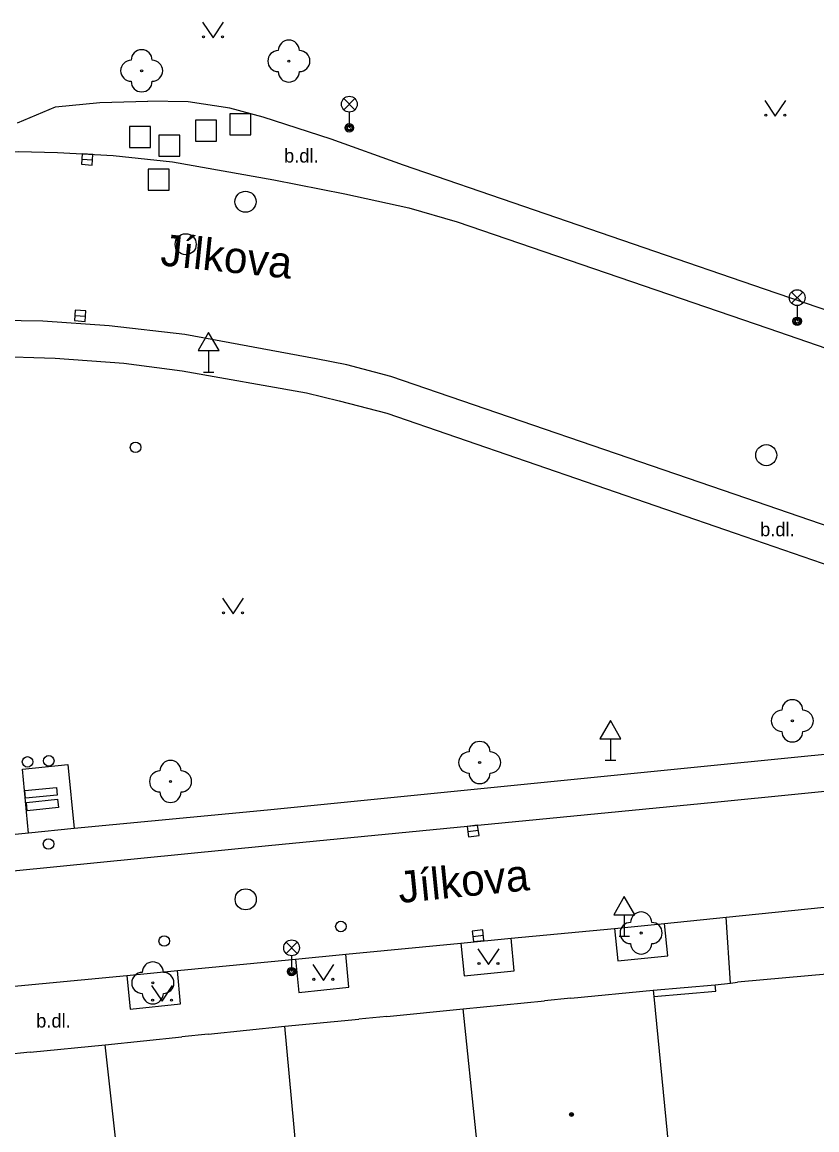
# Model space of a CAD drawing. Extents: x -596229 to -595156, y -1161237 to -1159376.
# Drawn here: x -596183.9 to -596146.2, y -1160892.5 to -1160839.9 of the extents above; entities that cross this region are included whole.
import ezdxf

# ---------------------------------------------------------------- set-up
doc = ezdxf.new("R2010")
doc.units = 0
for name, color, linetype in [('Level 22', 7, 'Continuous'), ('Level 26', 7, 'Continuous'), ('Level 27', 7, 'Continuous'), ('Level 28', 7, 'Continuous'), ('Level 31', 7, 'Continuous'), ('Level 33', 7, 'Continuous'), ('Level 34', 7, 'Continuous'), ('Level 36', 7, 'Continuous'), ('Level 39', 7, 'Continuous'), ('Nazvy ulic', 7, 'Continuous'), ('plynovod - povrch.  znaky - PRIS skut. velikost', 7, 'Continuous'), ('TM - budovy zdene_ betonove - VP', 7, 'Continuous'), ('TM - chodniky - VP', 7, 'Continuous'), ('TM - komunikace - VP', 7, 'Continuous'), ('TM - plot drateny_ kovovy - VP', 7, 'Continuous'), ('TM - plot zdeny_ ohradni zed - VP', 7, 'Continuous'), ('TM - podezdivka plotu - VP', 7, 'Continuous'), ('TM - popis povrchu', 7, 'Continuous'), ('TM - rozhrani mezi zpev. plochami mezi sebou - VP', 7, 'Continuous'), ('TM - rozhrani ploch obecne - VP', 7, 'Continuous'), ('TM - vjezd na pozemek', 7, 'Continuous'), ('TM - vstup do budovy - zdene_ betonove', 7, 'Continuous')]:
    doc.layers.add(name, color=color, linetype=linetype)

msp = doc.modelspace()

# ---------------------------------------------------------------- linework, layer by layer
at = {"layer": 'Level 22'}
for centre in [(-596171.24, -1160841.74), (-596178.23, -1160842.2), (-596147.33, -1160873.08), (-596162.18, -1160875.06), (-596176.86, -1160875.96), (-596154.51, -1160883.16), (-596177.7, -1160885.53)]:
    msp.add_circle(centre, 0.05, dxfattribs=at)
for centre, start, end in [((-596171.24, -1160841.24), 0, 180), ((-596178.23, -1160841.7), 0, 180), ((-596171.74, -1160841.74), 90, 270), ((-596170.74, -1160841.74), 270, 90), ((-596178.73, -1160842.2), 90, 270), ((-596177.73, -1160842.2), 270, 90), ((-596171.24, -1160842.24), 180, 0), ((-596178.23, -1160842.7), 180, 0), ((-596147.33, -1160872.58), 0, 180), ((-596147.83, -1160873.08), 90, 270), ((-596146.83, -1160873.08), 270, 90), ((-596147.33, -1160873.58), 180, 0), ((-596162.18, -1160874.56), 0, 180), ((-596176.86, -1160875.46), 0, 180), ((-596162.68, -1160875.06), 90, 270), ((-596161.68, -1160875.06), 270, 90), ((-596177.36, -1160875.96), 90, 270), ((-596176.36, -1160875.96), 270, 90), ((-596162.18, -1160875.56), 180, 0), ((-596176.86, -1160876.46), 180, 0), ((-596154.51, -1160882.66), 0, 180), ((-596155.01, -1160883.16), 90, 270), ((-596154.01, -1160883.16), 270, 90), ((-596154.51, -1160883.66), 180, 0), ((-596177.7, -1160885.03), 0, 180), ((-596178.2, -1160885.53), 90, 270), ((-596177.2, -1160885.53), 270, 90), ((-596177.7, -1160886.03), 180, 0)]:
    msp.add_arc(centre, 0.5, start, end, dxfattribs=at)
at = {"layer": 'Level 26'}
for points in [[(-596174.05, -1160845.24), (-596173.05, -1160845.24), (-596173.05, -1160844.24), (-596174.05, -1160844.24)], [(-596178.81, -1160845.84), (-596177.81, -1160845.84), (-596177.81, -1160844.84), (-596178.81, -1160844.84)], [(-596175.67, -1160845.54), (-596174.67, -1160845.54), (-596174.67, -1160844.54), (-596175.67, -1160844.54)], [(-596177.42, -1160846.26), (-596176.42, -1160846.26), (-596176.42, -1160845.26), (-596177.42, -1160845.26)], [(-596177.92, -1160847.87), (-596176.92, -1160847.87), (-596176.92, -1160846.87), (-596177.92, -1160846.87)]]:
    msp.add_lwpolyline(points, close=True, dxfattribs=at)
at = {"layer": 'Level 27'}
for p, q in [((-596181.069, -1160846.393), (-596180.571, -1160846.426)), ((-596181.399, -1160853.82), (-596180.901, -1160853.86)), ((-596162.738, -1160878.342), (-596162.242, -1160878.278)), ((-596162.498, -1160883.318), (-596162.002, -1160883.262))]:
    msp.add_line(p, q, dxfattribs=at)
for points in [[(-596181.086, -1160846.643), (-596180.587, -1160846.676), (-596180.554, -1160846.177), (-596181.053, -1160846.144)], [(-596181.419, -1160854.07), (-596180.92, -1160854.109), (-596180.881, -1160853.61), (-596181.38, -1160853.571)], [(-596162.706, -1160878.59), (-596162.21, -1160878.526), (-596162.274, -1160878.03), (-596162.77, -1160878.094)], [(-596162.47, -1160883.567), (-596161.973, -1160883.51), (-596162.03, -1160883.013), (-596162.527, -1160883.07)]]:
    msp.add_lwpolyline(points, close=True, dxfattribs=at)
for centre in [(-596173.3, -1160848.42), (-596176.14, -1160850.44), (-596148.57, -1160860.46), (-596173.29, -1160881.56)]:
    msp.add_circle(centre, 0.5, dxfattribs=at)
at = {"layer": 'Level 28'}
for centre in [(-596168.77, -1160882.85), (-596177.16, -1160883.54)]:
    msp.add_circle(centre, 0.25, dxfattribs=at)
at = {"layer": 'Level 31'}
for centre in [(-596178.52, -1160860.09), (-596183.65, -1160875.03), (-596182.64, -1160874.98), (-596182.65, -1160878.93)]:
    msp.add_circle(centre, 0.25, dxfattribs=at)
at = {"layer": 'Level 33'}
for p, q in [((-596168.635, -1160844.05), (-596168.105, -1160843.52)), ((-596168.635, -1160843.52), (-596168.105, -1160844.05)), ((-596168.37, -1160844.16), (-596168.37, -1160844.91)), ((-596147.365, -1160853.24), (-596146.835, -1160852.71)), ((-596147.365, -1160852.71), (-596146.835, -1160853.24)), ((-596147.1, -1160853.35), (-596147.1, -1160854.1)), ((-596171.375, -1160884.13), (-596170.845, -1160883.6)), ((-596171.375, -1160883.6), (-596170.845, -1160884.13)), ((-596171.11, -1160884.24), (-596171.11, -1160884.99))]:
    msp.add_line(p, q, dxfattribs=at)
for centre, radius in [((-596168.37, -1160843.785), 0.375), ((-596168.37, -1160844.91), 0.2), ((-596168.37, -1160844.91), 0.145), ((-596168.37, -1160844.91), 0.0876), ((-596147.1, -1160852.975), 0.375), ((-596147.1, -1160854.1), 0.2), ((-596147.1, -1160854.1), 0.145), ((-596147.1, -1160854.1), 0.0876), ((-596171.11, -1160883.865), 0.375), ((-596171.11, -1160884.99), 0.2), ((-596171.11, -1160884.99), 0.145), ((-596171.11, -1160884.99), 0.0876)]:
    msp.add_circle(centre, radius, dxfattribs=at)
at = {"layer": 'Level 34'}
for p, q in [((-596175.05, -1160855.492), (-596175.05, -1160856.51)), ((-596175.3, -1160856.51), (-596174.8, -1160856.51)), ((-596155.97, -1160873.932), (-596155.97, -1160874.95)), ((-596156.22, -1160874.95), (-596155.72, -1160874.95)), ((-596155.31, -1160882.292), (-596155.31, -1160883.31)), ((-596155.56, -1160883.31), (-596155.06, -1160883.31))]:
    msp.add_line(p, q, dxfattribs=at)
for points in [[(-596175.55, -1160855.492), (-596174.55, -1160855.492), (-596175.05, -1160854.626)], [(-596156.47, -1160873.932), (-596155.47, -1160873.932), (-596155.97, -1160873.066)], [(-596155.81, -1160882.292), (-596154.81, -1160882.292), (-596155.31, -1160881.426)]]:
    msp.add_lwpolyline(points, close=True, dxfattribs=at)
at = {"layer": 'Level 36'}
for points in [[(-596175.34, -1160839.89), (-596174.84, -1160840.64), (-596174.34, -1160839.89)], [(-596148.64, -1160843.61), (-596148.14, -1160844.36), (-596147.64, -1160843.61)], [(-596174.39, -1160867.25), (-596173.89, -1160868), (-596173.39, -1160867.25)], [(-596162.26, -1160883.91), (-596161.76, -1160884.66), (-596161.26, -1160883.91)], [(-596170.1, -1160884.66), (-596169.6, -1160885.41), (-596169.1, -1160884.66)], [(-596177.76, -1160885.65), (-596177.26, -1160886.4), (-596176.76, -1160885.65)]]:
    msp.add_lwpolyline(points, dxfattribs=at)
for centre in [(-596175.29, -1160840.59), (-596174.391, -1160840.59), (-596148.59, -1160844.31), (-596147.691, -1160844.31), (-596174.34, -1160867.95), (-596173.441, -1160867.95), (-596162.21, -1160884.61), (-596161.311, -1160884.61), (-596170.05, -1160885.36), (-596169.151, -1160885.36), (-596177.71, -1160886.35), (-596176.811, -1160886.35)]:
    msp.add_circle(centre, 0.05, dxfattribs=at)
at = {"layer": 'Level 39'}
for radius in [0.09, 0.0398]:
    msp.add_circle((-596157.82, -1160891.78), radius, dxfattribs=at)
at = {"layer": 'plynovod - povrch.  znaky - PRIS skut. velikost'}
for points in [[(-596183.78, -1160876.39), (-596182.28, -1160876.24), (-596182.24, -1160876.61), (-596183.74, -1160876.76), (-596183.78, -1160876.39)], [(-596183.7, -1160876.96), (-596182.22, -1160876.8), (-596182.18, -1160877.2), (-596183.66, -1160877.36), (-596183.7, -1160876.96)]]:
    msp.add_lwpolyline(points, dxfattribs=at)
at = {"layer": 'TM - budovy zdene_ betonove - VP'}
for points in [[(-596157.85, -1160886.26), (-596153.94, -1160885.87)], [(-596153.94, -1160885.87), (-596153.91, -1160886.17)], [(-596162.96, -1160886.76), (-596159.1, -1160886.38)], [(-596153.91, -1160886.17), (-596152.77, -1160897.86)], [(-596166.59, -1160887.12), (-596162.96, -1160886.76)], [(-596161.73, -1160898.67), (-596162.96, -1160886.76)], [(-596175.07, -1160887.97), (-596171.43, -1160887.59)], [(-596171.43, -1160887.59), (-596167.92, -1160887.25)], [(-596170.34, -1160899.44), (-596171.43, -1160887.59)], [(-596179.97, -1160888.47), (-596176.32, -1160888.09)], [(-596183.53, -1160888.82), (-596179.97, -1160888.47)], [(-596178.65, -1160900.3), (-596179.97, -1160888.47)]]:
    msp.add_lwpolyline(points, dxfattribs=at)
at = {"layer": 'TM - chodniky - VP'}
for points in [[(-596184.13, -1160844.68), (-596182.32, -1160843.92), (-596180.22, -1160843.7), (-596177.93, -1160843.65)], [(-596165.8, -1160846.69), (-596169.23, -1160845.45), (-596172.46, -1160844.41), (-596174.04, -1160843.97), (-596176.02, -1160843.68), (-596177.93, -1160843.65)], [(-596128.17, -1160859.58), (-596148.65, -1160852.57), (-596165.8, -1160846.69)], [(-596185.38, -1160855.75), (-596182.33, -1160855.85), (-596179.07, -1160856.09), (-596176.3, -1160856.45), (-596170.4, -1160857.5), (-596168.85, -1160857.88), (-596166.59, -1160858.47), (-596150.05, -1160864.16), (-596134.43, -1160869.55)], [(-596134.82, -1160873.59), (-596151.2, -1160875.22), (-596172.26, -1160877.32), (-596181.44, -1160878.2)], [(-596183.6, -1160878.41), (-596197.53, -1160879.81)], [(-596181.44, -1160878.2), (-596183.6, -1160878.41)], [(-596155.77, -1160882.94), (-596155.62, -1160884.48), (-596153.25, -1160884.24), (-596153.4, -1160882.71)], [(-596163.07, -1160883.64), (-596162.92, -1160885.2), (-596160.54, -1160884.96), (-596160.69, -1160883.41)], [(-596170.92, -1160884.4), (-596170.77, -1160885.98), (-596168.39, -1160885.73), (-596168.54, -1160884.17)], [(-596178.93, -1160885.17), (-596178.78, -1160886.77), (-596176.38, -1160886.53), (-596176.53, -1160884.94)]]:
    msp.add_lwpolyline(points, dxfattribs=at)
at = {"layer": 'TM - komunikace - VP'}
for points in [[(-596186.89, -1160846.14), (-596184.08, -1160846.04), (-596182.22, -1160846.08), (-596179.59, -1160846.23), (-596176.77, -1160846.52), (-596171.95, -1160847.38), (-596168.58, -1160848.04), (-596165.55, -1160848.71), (-596163.24, -1160849.38), (-596148.49, -1160854.43)], [(-596133.33, -1160868.07), (-596150.05, -1160862.33), (-596166.39, -1160856.73), (-596168.48, -1160856.17), (-596169.95, -1160855.88), (-596176.18, -1160854.72), (-596179.77, -1160854.31), (-596182.93, -1160854.09), (-596186.03, -1160854.05)], [(-596148.49, -1160854.43), (-596128.71, -1160861.25)], [(-596198.39, -1160881.6), (-596172.2, -1160879.01), (-596151.02, -1160876.94), (-596134.66, -1160875.31)], [(-596150.48, -1160882.41), (-596140.54, -1160881.39)], [(-596155.77, -1160882.94), (-596153.4, -1160882.71)], [(-596153.4, -1160882.71), (-596150.48, -1160882.41)], [(-596160.69, -1160883.41), (-596155.77, -1160882.94)], [(-596168.54, -1160884.17), (-596163.07, -1160883.64)], [(-596163.07, -1160883.64), (-596160.69, -1160883.41)], [(-596176.53, -1160884.94), (-596170.92, -1160884.4)], [(-596170.92, -1160884.4), (-596168.54, -1160884.17)], [(-596178.93, -1160885.17), (-596176.53, -1160884.94)], [(-596185.13, -1160885.77), (-596178.93, -1160885.17)]]:
    msp.add_lwpolyline(points, dxfattribs=at)
at = {"layer": 'TM - plot drateny_ kovovy - VP'}
for points in [[(-596150.26, -1160885.54), (-596149.94, -1160885.5)], [(-596150.99, -1160885.62), (-596150.26, -1160885.54)]]:
    msp.add_lwpolyline(points, dxfattribs=at)
at = {"layer": 'TM - plot zdeny_ ohradni zed - VP'}
msp.add_lwpolyline([(-596153.91, -1160886.17), (-596150.97, -1160885.92), (-596150.99, -1160885.62)], dxfattribs=at)
at = {"layer": 'TM - podezdivka plotu - VP'}
msp.add_lwpolyline([(-596153.94, -1160885.87), (-596150.99, -1160885.62)], dxfattribs=at)
at = {"layer": 'TM - rozhrani mezi zpev. plochami mezi sebou - VP'}
msp.add_lwpolyline([(-596150.26, -1160885.54), (-596150.48, -1160882.41)], dxfattribs=at)
at = {"layer": 'TM - rozhrani ploch obecne - VP'}
msp.add_lwpolyline([(-596183.6, -1160878.41), (-596183.89, -1160875.37), (-596181.73, -1160875.16), (-596181.44, -1160878.2)], dxfattribs=at)
at = {"layer": 'TM - vjezd na pozemek'}
msp.add_lwpolyline([(-596144.45, -1160885), (-596149.94, -1160885.5)], dxfattribs=at)
at = {"layer": 'TM - vstup do budovy - zdene_ betonove'}
for points in [[(-596157.85, -1160886.26), (-596159.1, -1160886.38)], [(-596166.59, -1160887.12), (-596167.92, -1160887.25)], [(-596175.07, -1160887.97), (-596176.32, -1160888.09)], [(-596183.53, -1160888.82), (-596184.75, -1160888.94)]]:
    msp.add_lwpolyline(points, dxfattribs=at)

# ---------------------------------------------------------------- texts
at = {"layer": 'Nazvy ulic'}
for rotation, p in [(354.0861, (-596177.373, -1160851.438)), (5.7152, (-596165.985, -1160881.741))]:
    msp.add_text('Jílkova', height=1.5, rotation=rotation, dxfattribs=at).set_placement(p)
at = {"layer": 'TM - popis povrchu'}
for p in [(-596171.47, -1160846.56), (-596148.86, -1160864.31), (-596183.24, -1160887.65)]:
    msp.add_text('b.dl.', height=0.65, dxfattribs=at).set_placement(p)

doc.saveas('drawing.dxf')
